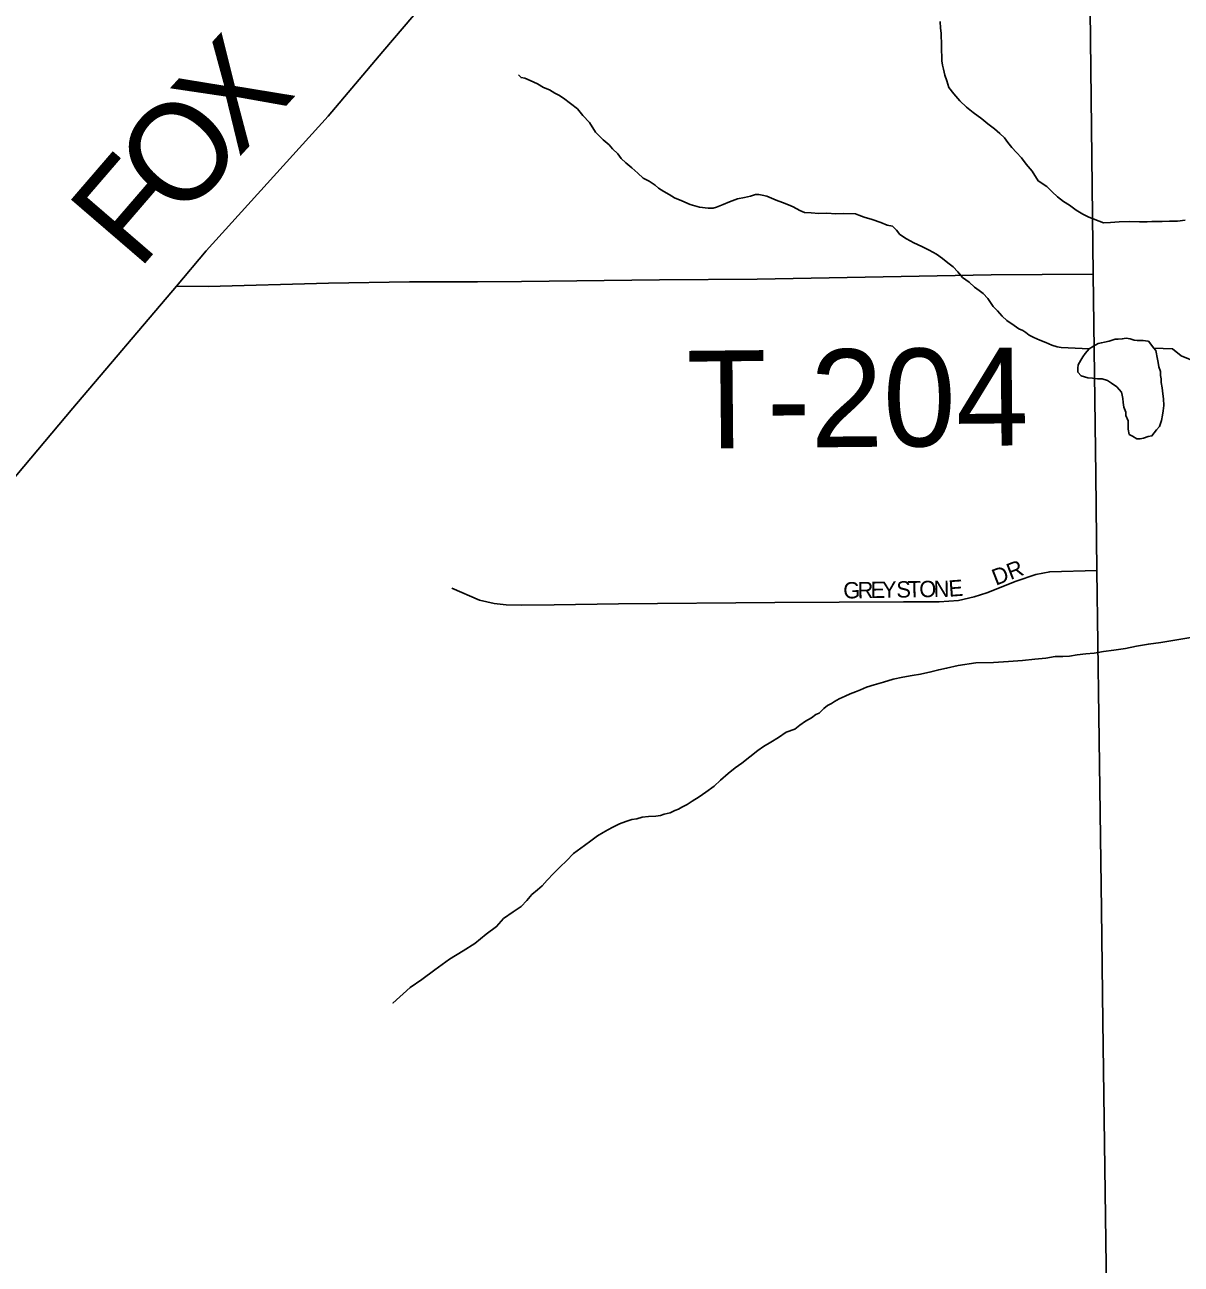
# Model space of a CAD drawing. Extents: x 0 to 34, y 0 to 22.
# Drawn here: x 4.841 to 5.513, y 14.815 to 15.535 of the extents above; entities that cross this region are included whole.
import ezdxf

# ---------------------------------------------------------------- set-up
doc = ezdxf.new("R2010")
doc.units = 0
for name, color, linetype in [('GM_X_County_Road', 7, 'Continuous'), ('GM_X_Minor_Lake', 7, 'Continuous'), ('GM_X_Minor_River', 7, 'Continuous'), ('GM_X_Township_Road', 7, 'Continuous'), ('GM_X_Township_Road_Text', 7, 'Continuous'), ('GM_X_Township_Subdivision', 7, 'Continuous'), ('GM_X_Township_Subdivision_Text', 7, 'Continuous')]:
    doc.layers.add(name, color=color, linetype=linetype)

msp = doc.modelspace()

# ---------------------------------------------------------------- linework, layer by layer
at = {"layer": 'GM_X_County_Road'}
msp.add_lwpolyline([(5.43519, 17.01039), (5.43643, 16.96899), (5.43802, 16.87954), (5.4412, 16.66966), (5.4449, 16.45423), (5.44914, 16.24038), (5.45099, 16.14484), (5.45152, 16.09217), (5.4532, 16.0369), (5.45433, 15.99673), (5.45635, 15.86789), (5.45792, 15.71617), (5.45994, 15.57746), (5.46196, 15.39004), (5.46353, 15.27333), (5.4642, 15.21767), (5.46532, 15.13327), (5.4669, 15.0206), (5.46757, 14.95573), (5.47004, 14.7856), (5.47206, 14.60492), (5.47453, 14.43367), (5.47558, 14.33849)], dxfattribs=at)
at = {"layer": 'GM_X_Minor_Lake'}
for points in [[(5.49417, 15.35113), (5.49379, 15.35112), (5.49111, 15.35144), (5.48769, 15.35137), (5.48578, 15.35171), (5.48348, 15.35241), (5.48119, 15.35274), (5.47892, 15.35231), (5.47664, 15.35226), (5.47473, 15.35221), (5.47134, 15.35099), (5.46869, 15.35055), (5.46679, 15.35013), (5.4649, 15.34971), (5.46227, 15.34813), (5.45964, 15.34654), (5.45742, 15.34383), (5.45595, 15.34189), (5.45485, 15.33996), (5.45339, 15.33727), (5.45305, 15.33536), (5.4531, 15.33308), (5.45506, 15.33084), (5.45889, 15.32978), (5.46156, 15.32946), (5.46461, 15.32915), (5.46727, 15.32921), (5.47034, 15.32814), (5.47266, 15.32667), (5.47575, 15.32446), (5.47848, 15.32148), (5.47891, 15.31958), (5.47933, 15.31769)], [(5.49417, 15.35113), (5.49379, 15.35112), (5.49111, 15.35144), (5.48769, 15.35137), (5.48578, 15.35171), (5.48348, 15.35241), (5.48119, 15.35274), (5.47892, 15.35231), (5.47664, 15.35226), (5.47473, 15.35221), (5.47134, 15.35099), (5.46869, 15.35055), (5.46679, 15.35013), (5.4649, 15.34971), (5.46227, 15.34813), (5.45964, 15.34654), (5.45742, 15.34383), (5.45595, 15.34189), (5.45485, 15.33996), (5.45339, 15.33727), (5.45305, 15.33536), (5.4531, 15.33308), (5.45506, 15.33084), (5.45889, 15.32978), (5.46156, 15.32946), (5.46461, 15.32915), (5.46727, 15.32921), (5.47034, 15.32814), (5.47266, 15.32667), (5.47575, 15.32446), (5.47848, 15.32148), (5.47891, 15.31958), (5.47933, 15.31769), (5.47938, 15.31541), (5.47982, 15.31275), (5.48103, 15.30974), (5.48108, 15.30784), (5.48229, 15.30482), (5.48234, 15.30254), (5.4824, 15.29988), (5.48285, 15.29684), (5.48478, 15.29574), (5.48748, 15.29428), (5.48937, 15.29433), (5.49127, 15.29475), (5.49391, 15.29557), (5.49619, 15.296), (5.49877, 15.29949), (5.50063, 15.30143), (5.50169, 15.30488), (5.50238, 15.30794), (5.5027, 15.31061), (5.50301, 15.31366), (5.50292, 15.31747), (5.50248, 15.3205), (5.50202, 15.32392), (5.50157, 15.32695), (5.50152, 15.32923), (5.50109, 15.33112), (5.50104, 15.33341), (5.50022, 15.33605), (5.49978, 15.3387), (5.49935, 15.3406), (5.49848, 15.34552), (5.4973, 15.34702), (5.49417, 15.35113)], [(5.47933, 15.31769), (5.47938, 15.31541), (5.47982, 15.31275), (5.48103, 15.30974), (5.48108, 15.30784), (5.48229, 15.30482), (5.48234, 15.30254), (5.4824, 15.29988), (5.48285, 15.29684), (5.48478, 15.29574), (5.48748, 15.29428), (5.48937, 15.29433), (5.49127, 15.29475), (5.49391, 15.29557), (5.49619, 15.296), (5.49877, 15.29949), (5.50063, 15.30143), (5.50169, 15.30488), (5.50238, 15.30794), (5.5027, 15.31061), (5.50301, 15.31366), (5.50292, 15.31747), (5.50248, 15.3205), (5.50202, 15.32392), (5.50157, 15.32695), (5.50152, 15.32923), (5.50109, 15.33112), (5.50104, 15.33341), (5.50022, 15.33605), (5.49978, 15.3387), (5.49935, 15.3406), (5.49848, 15.34552), (5.4973, 15.34702), (5.49417, 15.35113)]]:
    msp.add_lwpolyline(points, dxfattribs=at)
at = {"layer": 'GM_X_Minor_River'}
for points in [[(5.37321, 15.53683), (5.3733, 15.53303), (5.37375, 15.52999), (5.3738, 15.52771), (5.37386, 15.52505), (5.37391, 15.52315), (5.37398, 15.51972), (5.37405, 15.51668), (5.37411, 15.51402), (5.37455, 15.51136), (5.37499, 15.50909), (5.37583, 15.50569), (5.37705, 15.50229), (5.37827, 15.49851), (5.38102, 15.49477), (5.38454, 15.49066), (5.38843, 15.48695), (5.3923, 15.48399), (5.39734, 15.4803), (5.40083, 15.47734), (5.4047, 15.47438), (5.4078, 15.47179), (5.41052, 15.46918), (5.41249, 15.46657), (5.41484, 15.46357), (5.41757, 15.46059), (5.4203, 15.45761), (5.42305, 15.45387), (5.42657, 15.44976), (5.43012, 15.44414), (5.43514, 15.44083), (5.43826, 15.43785), (5.44137, 15.43488), (5.44485, 15.4323), (5.44833, 15.43009), (5.4522, 15.42714), (5.45605, 15.42494), (5.45952, 15.42312)], [(5.12812, 15.50574), (5.12968, 15.50426), (5.13197, 15.50393), (5.13505, 15.50248), (5.13927, 15.50067), (5.14275, 15.49847), (5.1462, 15.49703), (5.14929, 15.49519), (5.1516, 15.4941), (5.1543, 15.49226), (5.16244, 15.48598), (5.16557, 15.48225), (5.16947, 15.47815), (5.17302, 15.47252), (5.17731, 15.46806), (5.1808, 15.46509), (5.18275, 15.46285), (5.18587, 15.45988), (5.18783, 15.45726), (5.19055, 15.45466), (5.19404, 15.45169), (5.19753, 15.44873), (5.20065, 15.44576), (5.20411, 15.44393), (5.20759, 15.44173), (5.20953, 15.43987), (5.21262, 15.43804), (5.2157, 15.43621), (5.21879, 15.43438), (5.22302, 15.43257), (5.22801, 15.4304), (5.23337, 15.429), (5.23833, 15.42835), (5.24138, 15.42842), (5.24327, 15.42885), (5.24704, 15.43045), (5.2508, 15.43206), (5.25533, 15.43369), (5.2595, 15.43454), (5.26291, 15.43538), (5.26593, 15.43621), (5.26783, 15.43625), (5.26974, 15.43592), (5.27242, 15.43522), (5.2778, 15.43306), (5.28163, 15.43162), (5.28509, 15.43018), (5.28778, 15.4291), (5.29164, 15.4269), (5.29432, 15.42582), (5.29813, 15.42553), (5.30271, 15.42525), (5.30727, 15.42536), (5.3126, 15.4251), (5.31717, 15.4252), (5.32402, 15.42498), (5.32594, 15.42426), (5.32901, 15.42319), (5.33361, 15.42177), (5.33859, 15.41998), (5.34243, 15.41855), (5.34549, 15.41785), (5.34783, 15.41563), (5.34979, 15.41301), (5.35365, 15.41043), (5.35789, 15.40824), (5.3625, 15.40607), (5.36674, 15.40388), (5.37098, 15.40169), (5.37446, 15.39911), (5.37756, 15.39652), (5.38066, 15.3943), (5.38339, 15.39132), (5.38613, 15.38796), (5.38999, 15.38538), (5.3931, 15.38241), (5.39581, 15.38057), (5.39813, 15.37872), (5.40087, 15.37574), (5.40244, 15.37349), (5.40401, 15.37124), (5.40636, 15.36863), (5.40909, 15.36565), (5.41181, 15.36305), (5.41606, 15.3601), (5.41877, 15.35826), (5.42108, 15.35717), (5.423, 15.35607), (5.42494, 15.3546), (5.42764, 15.35314), (5.43109, 15.35169), (5.43455, 15.35025), (5.43801, 15.34881), (5.44108, 15.34773), (5.44337, 15.34741), (5.45964, 15.34654)], [(5.45952, 15.42312), (5.46796, 15.41988), (5.47215, 15.41998), (5.47708, 15.42047), (5.48317, 15.42061), (5.48888, 15.42036), (5.49344, 15.42046), (5.49611, 15.42053), (5.49915, 15.42059), (5.50219, 15.42066), (5.50637, 15.42076), (5.51094, 15.42086), (5.51549, 15.42135)], [(5.4973, 15.34702), (5.50807, 15.3466), (5.51311, 15.34253), (5.52271, 15.33856)], [(5.05523, 14.96641), (5.06529, 14.97539), (5.05523, 14.96641), (5.06529, 14.97539), (5.07203, 14.98011), (5.07952, 14.98561), (5.08813, 14.99189), (5.09601, 14.99664), (5.10276, 15.00098), (5.10948, 15.00646), (5.11547, 15.01078), (5.11955, 15.01544), (5.12517, 15.01938), (5.12966, 15.02252), (5.133, 15.02602), (5.13597, 15.02952), (5.13933, 15.03226), (5.14194, 15.0346), (5.14491, 15.03771), (5.14863, 15.0416), (5.15235, 15.04549), (5.15607, 15.049), (5.16016, 15.05328), (5.16652, 15.05799), (5.17026, 15.06074), (5.174, 15.06349), (5.17738, 15.06547), (5.18001, 15.06705), (5.18302, 15.06864), (5.18678, 15.07063), (5.19055, 15.07186), (5.19395, 15.07308), (5.19698, 15.07353), (5.20001, 15.07436), (5.2038, 15.07482), (5.20798, 15.07492), (5.21064, 15.07536), (5.2129, 15.07617), (5.21631, 15.07701), (5.21894, 15.07821), (5.22121, 15.07903), (5.22308, 15.08021), (5.22609, 15.0818), (5.22909, 15.08377), (5.23322, 15.08615), (5.23696, 15.0889), (5.24183, 15.09243), (5.24555, 15.09594), (5.25003, 15.09985), (5.25414, 15.10299), (5.25789, 15.10574), (5.26723, 15.11318), (5.2706, 15.11554), (5.27473, 15.11792), (5.27923, 15.12068), (5.28373, 15.12383), (5.28864, 15.12546), (5.29162, 15.12782), (5.295, 15.13017), (5.29837, 15.13215), (5.30099, 15.13412), (5.30288, 15.13492), (5.30548, 15.13764), (5.30773, 15.13922), (5.30998, 15.14041), (5.31186, 15.14159), (5.31448, 15.14318), (5.31787, 15.14478), (5.32089, 15.14599), (5.32391, 15.1472), (5.32692, 15.14841), (5.33031, 15.15), (5.33485, 15.15125), (5.34014, 15.15289), (5.34581, 15.15454), (5.35148, 15.15582), (5.35679, 15.1567), (5.36172, 15.15757), (5.36777, 15.15885), (5.37231, 15.16009), (5.37686, 15.16096), (5.38367, 15.16264), (5.39391, 15.16401), (5.40418, 15.16425), (5.41292, 15.16483), (5.4209, 15.16539), (5.4281, 15.16631), (5.43456, 15.16684), (5.43987, 15.16772), (5.44443, 15.16782), (5.44823, 15.16791), (5.45278, 15.16878), (5.45772, 15.16927), (5.46265, 15.16976), (5.46796, 15.17064), (5.47402, 15.17154), (5.48085, 15.17246), (5.48729, 15.17375), (5.49411, 15.17504), (5.50132, 15.17597), (5.52331, 15.17951)]]:
    msp.add_lwpolyline(points, dxfattribs=at)
at = {"layer": 'GM_X_Township_Road'}
for points in [[(5.10778, 15.58823), (5.04942, 15.51932), (5.01755, 15.48184), (4.99713, 15.45917), (4.94673, 15.40361), (4.92957, 15.38308), (4.86941, 15.31216), (4.79086, 15.21901), (4.76011, 15.18265), (4.70751, 15.12058), (4.67773, 15.08457), (4.63374, 15.03452), (4.59402, 14.98805), (4.55519, 14.94339), (4.46586, 14.83857), (4.4562, 14.82757)], [(5.46196, 15.39004), (5.4027, 15.38959), (5.26691, 15.38712), (5.21008, 15.38672), (5.13, 15.38578), (5.10441, 15.38547), (5.06491, 15.38555), (5.01777, 15.38466), (4.94797, 15.38286), (4.92957, 15.38308)]]:
    msp.add_lwpolyline(points, dxfattribs=at)
at = {"layer": 'GM_X_Township_Subdivision'}
msp.add_lwpolyline([(5.4642, 15.21767), (5.43682, 15.21699), (5.42874, 15.21542), (5.41729, 15.21161), (5.40023, 15.20487), (5.39283, 15.2024), (5.38385, 15.20038), (5.37263, 15.19949), (5.35175, 15.19949), (5.27711, 15.19921), (5.18632, 15.19846), (5.14901, 15.19789), (5.12996, 15.19762), (5.12096, 15.19789), (5.11408, 15.19868), (5.10561, 15.20053), (5.08946, 15.20742)], dxfattribs=at)

# ---------------------------------------------------------------- texts
at = {"layer": 'GM_X_Township_Road_Text'}
for s, height, rotation, p in [('X', 0.05682, 47.60502, (4.96549, 15.45733)), ('O', 0.05682, 47.92234, (4.93204, 15.42028)), ('F', 0.05682, 49.26419, (4.90725, 15.3915)), ('T-204', 0.056818, 0.56105, (5.22625, 15.28858))]:
    msp.add_text(s, height=height, rotation=rotation, dxfattribs=at).set_placement(p)
at = {"layer": 'GM_X_Township_Subdivision_Text'}
for s, rotation, p in [('DR', 21.25521, (5.40548, 15.20886)), ('G', 0.91805, (5.31692, 15.20148)), ('R', 0.95577, (5.32526, 15.20161)), ('E', 0.92889, (5.33276, 15.20174)), ('Y', 0.92786, (5.33943, 15.20185)), ('S', 0.93643, (5.34776, 15.20198)), ('T', 0.92889, (5.35442, 15.20209)), ('O', 0.92786, (5.36109, 15.2022)), ('N', 0.95035, (5.36943, 15.20233)), ('E', 4.21846, (5.37835, 15.20249))]:
    msp.add_text(s, height=0.00947, rotation=rotation, dxfattribs=at).set_placement(p)

doc.saveas('drawing.dxf')
